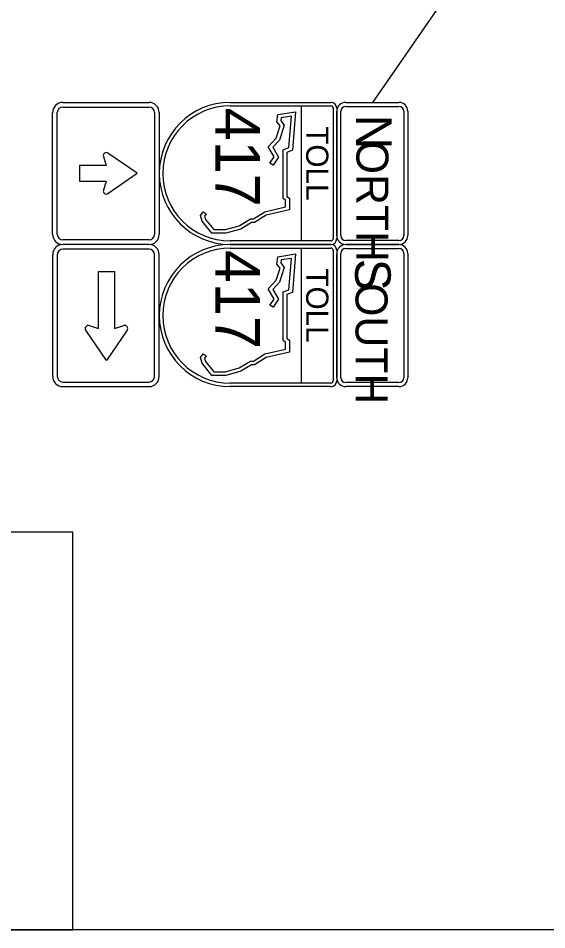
# Model space of a CAD drawing. Extents: x -830008.4 to -829992.7, y 1290284.1 to 1290294.4.
# Drawn here: x -830003.674 to -830002.168, y 1290285.328 to 1290287.925 of the extents above; entities that cross this region are included whole.
import ezdxf

# ---------------------------------------------------------------- set-up
doc = ezdxf.new("R2010")
doc.units = 0
for name, color, linetype in [('NonPlottingEle_dp', 7, 'Continuous'), ('SignPanel', 7, 'Continuous'), ('TextLabel', 7, 'Continuous')]:
    doc.layers.add(name, color=color, linetype=linetype)

msp = doc.modelspace()

# ---------------------------------------------------------------- linework, layer by layer
at = {"layer": 'NonPlottingEle_dp'}
msp.add_lwpolyline([(-830007.4742, 1290294.228), (-829992.7742, 1290294.228), (-829992.7742, 1290285.328), (-830007.4742, 1290285.328)], close=True, dxfattribs=at)
at = {"layer": 'SignPanel'}
for p, q in [((-830002.937, 1290287.6298), (-830002.9344, 1290287.6508)), ((-830002.9344, 1290287.6508), (-830002.8844, 1290287.6586)), ((-830002.9249, 1290287.6416), (-830002.926, 1290287.6329)), ((-830002.8959, 1290287.6461), (-830002.9249, 1290287.6416)), ((-830002.9028, 1290287.5566), (-830002.8959, 1290287.6461)), ((-830002.8844, 1290287.6586), (-830002.8928, 1290287.5492)), ((-830002.9393, 1290287.5838), (-830002.928, 1290287.6184)), ((-830002.928, 1290287.6184), (-830002.937, 1290287.6298)), ((-830002.9162, 1290287.6205), (-830002.93, 1290287.5783)), ((-830002.926, 1290287.6329), (-830002.9162, 1290287.6205)), ((-830002.9622, 1290287.559), (-830002.9393, 1290287.5838)), ((-830002.9451, 1290287.5299), (-830002.9622, 1290287.559)), ((-830002.93, 1290287.5783), (-830002.9491, 1290287.5576)), ((-830002.9491, 1290287.5576), (-830002.9326, 1290287.5295)), ((-830003.4317, 1290287.5317), (-830003.4239, 1290287.5056)), ((-830003.335, 1290287.4835), (-830003.4188, 1290287.5411)), ((-830002.9191, 1290287.5503), (-830002.9028, 1290287.5566)), ((-830002.9191, 1290287.4121), (-830002.9191, 1290287.5503)), ((-830002.8928, 1290287.5492), (-830002.9086, 1290287.5431)), ((-830002.9086, 1290287.5431), (-830002.9086, 1290287.4177)), ((-830003.4239, 1290287.5056), (-830003.4995, 1290287.5056)), ((-830003.4995, 1290287.5056), (-830003.4995, 1290287.4613)), ((-830002.9568, 1290287.5126), (-830002.9451, 1290287.5299)), ((-830002.9481, 1290287.5067), (-830002.9568, 1290287.5126)), ((-830002.9326, 1290287.5295), (-830002.9481, 1290287.5067)), ((-830003.4188, 1290287.4259), (-830003.335, 1290287.4835)), ((-830003.4995, 1290287.4613), (-830003.4239, 1290287.4613)), ((-830003.4239, 1290287.4613), (-830003.4317, 1290287.4353)), ((-830002.9121, 1290287.4073), (-830002.9191, 1290287.4121)), ((-830002.9121, 1290287.3876), (-830002.9121, 1290287.4073)), ((-830002.9086, 1290287.4177), (-830002.9016, 1290287.4129)), ((-830002.9016, 1290287.4129), (-830002.9016, 1290287.3792)), ((-830002.9714, 1290287.3738), (-830002.9121, 1290287.3876)), ((-830002.9016, 1290287.3792), (-830002.9673, 1290287.3639)), ((-830003.1544, 1290287.3636), (-830003.1472, 1290287.374)), ((-830003.1505, 1290287.3472), (-830003.1544, 1290287.3636)), ((-830003.1472, 1290287.374), (-830003.1385, 1290287.368)), ((-830003.1385, 1290287.368), (-830003.143, 1290287.3615)), ((-830003.143, 1290287.3615), (-830003.1408, 1290287.352)), ((-830003.1408, 1290287.352), (-830003.1172, 1290287.3232)), ((-830003.0444, 1290287.3341), (-830003.0121, 1290287.3536)), ((-830003.0121, 1290287.3536), (-830003.0038, 1290287.3536)), ((-830003.0038, 1290287.3536), (-830002.9714, 1290287.3738)), ((-830002.9673, 1290287.3639), (-830003.0007, 1290287.3431)), ((-830003.1222, 1290287.3127), (-830003.1505, 1290287.3472)), ((-830003.084, 1290287.3232), (-830003.0444, 1290287.3341)), ((-830003.0402, 1290287.3243), (-830003.0826, 1290287.3127)), ((-830003.0092, 1290287.3431), (-830003.0402, 1290287.3243)), ((-830003.0007, 1290287.3431), (-830003.0092, 1290287.3431)), ((-830003.0826, 1290287.3127), (-830003.1222, 1290287.3127)), ((-830003.1172, 1290287.3232), (-830003.084, 1290287.3232)), ((-830002.9344, 1290287.2458), (-830002.8844, 1290287.2536)), ((-830002.8844, 1290287.2536), (-830002.8928, 1290287.1442)), ((-830002.937, 1290287.2248), (-830002.9344, 1290287.2458)), ((-830002.928, 1290287.2134), (-830002.937, 1290287.2248)), ((-830002.9249, 1290287.2366), (-830002.926, 1290287.2279)), ((-830002.926, 1290287.2279), (-830002.9162, 1290287.2155)), ((-830002.8959, 1290287.2411), (-830002.9249, 1290287.2366)), ((-830002.9028, 1290287.1516), (-830002.8959, 1290287.2411)), ((-830003.4456, 1290287.0415), (-830003.4456, 1290287.2039)), ((-830003.4456, 1290287.2039), (-830003.4001, 1290287.2039)), ((-830003.4001, 1290287.2039), (-830003.4001, 1290287.0415)), ((-830002.9393, 1290287.1788), (-830002.928, 1290287.2134)), ((-830002.9162, 1290287.2155), (-830002.93, 1290287.1733)), ((-830002.9622, 1290287.154), (-830002.9393, 1290287.1788)), ((-830002.93, 1290287.1733), (-830002.9491, 1290287.1526)), ((-830002.9451, 1290287.1249), (-830002.9622, 1290287.154)), ((-830002.9491, 1290287.1526), (-830002.9326, 1290287.1245)), ((-830002.9191, 1290287.1453), (-830002.9028, 1290287.1516)), ((-830002.9191, 1290287.0071), (-830002.9191, 1290287.1453)), ((-830002.8928, 1290287.1442), (-830002.9086, 1290287.1381)), ((-830002.9568, 1290287.1076), (-830002.9451, 1290287.1249)), ((-830002.9326, 1290287.1245), (-830002.9481, 1290287.1017)), ((-830002.9086, 1290287.1381), (-830002.9086, 1290287.0127)), ((-830002.9481, 1290287.1017), (-830002.9568, 1290287.1076)), ((-830003.4724, 1290287.0495), (-830003.4456, 1290287.0415)), ((-830003.4001, 1290287.0415), (-830003.3732, 1290287.0495)), ((-830003.4228, 1290286.95), (-830003.4821, 1290287.0362)), ((-830003.3636, 1290287.0362), (-830003.4228, 1290286.95)), ((-830002.9086, 1290287.0127), (-830002.9016, 1290287.0079)), ((-830002.9121, 1290287.0023), (-830002.9191, 1290287.0071)), ((-830002.9121, 1290286.9826), (-830002.9121, 1290287.0023)), ((-830002.9016, 1290287.0079), (-830002.9016, 1290286.9742)), ((-830003.1544, 1290286.9586), (-830003.1472, 1290286.969)), ((-830003.1472, 1290286.969), (-830003.1385, 1290286.963)), ((-830003.1385, 1290286.963), (-830003.143, 1290286.9565)), ((-830003.0038, 1290286.9486), (-830002.9714, 1290286.9688)), ((-830002.9714, 1290286.9688), (-830002.9121, 1290286.9826)), ((-830002.9016, 1290286.9742), (-830002.9673, 1290286.9589)), ((-830003.1505, 1290286.9422), (-830003.1544, 1290286.9586)), ((-830003.1222, 1290286.9077), (-830003.1505, 1290286.9422)), ((-830003.143, 1290286.9565), (-830003.1408, 1290286.947)), ((-830003.1408, 1290286.947), (-830003.1172, 1290286.9182)), ((-830003.0444, 1290286.9291), (-830003.0121, 1290286.9486)), ((-830003.0092, 1290286.9381), (-830003.0402, 1290286.9193)), ((-830003.0121, 1290286.9486), (-830003.0038, 1290286.9486)), ((-830003.0007, 1290286.9381), (-830003.0092, 1290286.9381)), ((-830002.9673, 1290286.9589), (-830003.0007, 1290286.9381)), ((-830003.1172, 1290286.9182), (-830003.084, 1290286.9182)), ((-830003.084, 1290286.9182), (-830003.0444, 1290286.9291)), ((-830003.0402, 1290286.9193), (-830003.0826, 1290286.9077)), ((-830003.0826, 1290286.9077), (-830003.1222, 1290286.9077))]:
    msp.add_line(p, q, dxfattribs=at)
for points in [[(-830003.5473, 1290287.6856), (-830003.3015, 1290287.6856)], [(-830003.5473, 1290287.6723), (-830003.3014, 1290287.6723)], [(-830003.07, 1290287.6856), (-830002.7832, 1290287.6856)], [(-830003.07, 1290287.6754), (-830002.7832, 1290287.6754)], [(-830002.8675, 1290287.6754), (-830002.8675, 1290287.2907)], [(-830002.7764, 1290287.6687), (-830002.7764, 1290287.2974)], [(-830002.7663, 1290287.6687), (-830002.7663, 1290287.2974)], [(-830002.741, 1290287.6856), (-830002.5891, 1290287.6856)], [(-830002.741, 1290287.674), (-830002.5891, 1290287.674)], [(-830003.5763, 1290287.3095), (-830003.5763, 1290287.6566)], [(-830003.563, 1290287.3095), (-830003.563, 1290287.6566)], [(-830003.2858, 1290287.6566), (-830003.2858, 1290287.3095)], [(-830003.2725, 1290287.6566), (-830003.2725, 1290287.3095)], [(-830002.7663, 1290287.3059), (-830002.7663, 1290287.6603)], [(-830002.7547, 1290287.3059), (-830002.7547, 1290287.6603)], [(-830002.5754, 1290287.6603), (-830002.5754, 1290287.3059)], [(-830002.5638, 1290287.6603), (-830002.5638, 1290287.3059)], [(-830003.3014, 1290287.2938), (-830003.5473, 1290287.2938)], [(-830003.3015, 1290287.2806), (-830003.5473, 1290287.2806)], [(-830003.3015, 1290287.2806), (-830003.5473, 1290287.2806)], [(-830002.7832, 1290287.2907), (-830003.07, 1290287.2907)], [(-830002.7832, 1290287.2806), (-830003.07, 1290287.2806)], [(-830003.07, 1290287.2806), (-830002.7832, 1290287.2806)], [(-830002.5891, 1290287.2922), (-830002.741, 1290287.2922)], [(-830002.741, 1290287.2806), (-830002.5891, 1290287.2806)], [(-830002.5891, 1290287.2806), (-830002.741, 1290287.2806)], [(-830003.5763, 1290287.2516), (-830003.5763, 1290286.9045)], [(-830003.563, 1290287.2516), (-830003.563, 1290286.9045)], [(-830003.3014, 1290287.2673), (-830003.5473, 1290287.2673)], [(-830003.2858, 1290286.9045), (-830003.2858, 1290287.2516)], [(-830003.2725, 1290286.9045), (-830003.2725, 1290287.2516)], [(-830003.07, 1290287.2704), (-830002.7832, 1290287.2704)], [(-830002.8675, 1290287.2704), (-830002.8675, 1290286.8857)], [(-830002.7764, 1290287.2637), (-830002.7764, 1290286.8924)], [(-830002.7663, 1290287.2637), (-830002.7663, 1290286.8924)], [(-830002.7663, 1290286.9009), (-830002.7663, 1290287.2553)], [(-830002.7547, 1290286.9009), (-830002.7547, 1290287.2553)], [(-830002.741, 1290287.269), (-830002.5891, 1290287.269)], [(-830002.5754, 1290287.2553), (-830002.5754, 1290286.9009)], [(-830002.5638, 1290287.2553), (-830002.5638, 1290286.9009)], [(-830003.5473, 1290286.8888), (-830003.3014, 1290286.8888)], [(-830002.7832, 1290286.8857), (-830003.07, 1290286.8857)], [(-830002.5891, 1290286.8872), (-830002.741, 1290286.8872)], [(-830003.5473, 1290286.8756), (-830003.3015, 1290286.8756)], [(-830002.7832, 1290286.8756), (-830003.07, 1290286.8756)], [(-830002.5891, 1290286.8756), (-830002.741, 1290286.8756)]]:
    msp.add_lwpolyline(points, dxfattribs=at)
for centre, radius, start, end in [((-830003.5473, 1290287.6566), 0.0289, 90, 180), ((-830003.5473, 1290287.6566), 0.0157, 90, 180), ((-830003.3015, 1290287.6566), 0.0289, 360, 90), ((-830003.3015, 1290287.6566), 0.0157, 0, 89.9456), ((-830003.07, 1290287.4831), 0.2025, 90, 270), ((-830003.07, 1290287.4831), 0.1924, 90, 270), ((-830002.7832, 1290287.6687), 0.0169, 0, 90), ((-830002.7832, 1290287.6687), 0.00675, 0, 90), ((-830002.741, 1290287.6603), 0.0253, 90, 180), ((-830002.741, 1290287.6603), 0.0137, 90, 180), ((-830002.5891, 1290287.6603), 0.0253, 0, 90), ((-830002.5891, 1290287.6603), 0.0137, 0, 90), ((-830003.4236, 1290287.5341), 0.00844, 55.5119, 196.6443), ((-830003.4236, 1290287.4329), 0.00844, 163.3557, 304.4881), ((-830003.5473, 1290287.3095), 0.0289, 180, 270), ((-830003.5473, 1290287.3095), 0.0157, 180, 270), ((-830003.3015, 1290287.3095), 0.0289, 270, 0), ((-830003.3015, 1290287.3095), 0.0157, 270.0544, 0), ((-830002.741, 1290287.3059), 0.0253, 180, 270), ((-830002.741, 1290287.3059), 0.0137, 180, 270), ((-830002.5891, 1290287.3059), 0.0253, 270, 0), ((-830002.5891, 1290287.3059), 0.0137, 270, 0), ((-830003.5473, 1290287.2516), 0.0289, 90, 180), ((-830003.3015, 1290287.2516), 0.0289, 0, 90), ((-830003.07, 1290287.0781), 0.2025, 90, 270), ((-830002.7832, 1290287.2974), 0.0169, 270, 0), ((-830002.7832, 1290287.2974), 0.00675, 270, 0), ((-830002.7832, 1290287.2637), 0.0169, 0, 90), ((-830002.741, 1290287.2553), 0.0253, 90, 180), ((-830002.5891, 1290287.2553), 0.0253, 360, 90), ((-830003.5473, 1290287.2516), 0.0157, 90, 180), ((-830003.3015, 1290287.2516), 0.0157, 0, 89.9456), ((-830003.07, 1290287.0781), 0.1924, 90, 270), ((-830002.7832, 1290287.2637), 0.00675, 0, 90), ((-830002.741, 1290287.2553), 0.0137, 90, 180), ((-830002.5891, 1290287.2553), 0.0137, 360, 90), ((-830003.4749, 1290287.0412), 0.00868, 73.3557, 214.4881), ((-830003.3708, 1290287.0412), 0.00868, 325.5119, 106.6443), ((-830003.5473, 1290286.9045), 0.0289, 180, 270), ((-830003.5473, 1290286.9045), 0.0157, 180, 270), ((-830003.3015, 1290286.9045), 0.0289, 270, 0), ((-830003.3015, 1290286.9045), 0.0157, 270.0544, 0), ((-830002.7832, 1290286.8924), 0.0169, 270, 0), ((-830002.7832, 1290286.8924), 0.00675, 270, 0), ((-830002.741, 1290286.9009), 0.0253, 180, 270), ((-830002.741, 1290286.9009), 0.0137, 180, 270), ((-830002.5891, 1290286.9009), 0.0253, 270, 360), ((-830002.5891, 1290286.9009), 0.0137, 270, 360)]:
    msp.add_arc(centre, radius, start, end, dxfattribs=at)
at = {"layer": 'TextLabel'}
msp.add_line((-830001.6762, 1290289.1116), (-830002.665, 1290287.6856), dxfattribs=at)
msp.add_lwpolyline([(-830007.4742, 1290285.328), (-830003.5187, 1290285.328), (-830003.5187, 1290286.4608), (-830007.4742, 1290286.4608)], close=True, dxfattribs=at)

# ---------------------------------------------------------------- texts
at = {"layer": 'SignPanel'}
for s, height, p in [('417', 0.12656, (-830003.1122, 1290287.6704)), ('N', 0.1013, (-830002.7116, 1290287.65)), ('TOLL', 0.06328, (-830002.8536, 1290287.6175)), ('ORTH', 0.09113, (-830002.7104, 1290287.5762)), ('417', 0.12656, (-830003.1122, 1290287.2654)), ('S', 0.1013, (-830002.714, 1290287.2397)), ('TOLL', 0.06328, (-830002.8536, 1290287.2125)), ('OUTH', 0.09113, (-830002.7128, 1290287.1705))]:
    msp.add_text(s, height=height, rotation=270, dxfattribs=at).set_placement(p)

doc.saveas('drawing.dxf')
